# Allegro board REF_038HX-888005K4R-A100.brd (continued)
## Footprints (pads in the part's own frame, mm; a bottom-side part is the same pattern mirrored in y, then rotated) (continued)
PG_VG93K_F_HSM_G1D105_505_ND
  rect 1.626x1.626 smd: A1(-20.32,-3.81) A3(-15.24,-3.81) A5(-10.16,-3.81) A7(-5.08,-3.81) A9(0,-3.81) A11(5.08,-3.81) A13(10.16,-3.81) A15(15.24,-3.81) A17(20.32,-3.81) B2(-17.78,-1.27) B4(-12.7,-1.27) B6(-7.62,-1.27) B8(-2.54,-1.27) B10(2.54,-1.27) B12(7.62,-1.27) B14(12.7,-1.27) B16(17.78,-1.27) C1(-20.32,1.27) C3(-15.24,1.27) C5(-10.16,1.27) C7(-5.08,1.27) C9(0,1.27) C11(5.08,1.27) C13(10.16,1.27) C15(15.24,1.27) C17(20.32,1.27) D2(-17.78,3.81) D4(-12.7,3.81) D6(-7.62,3.81) D8(-2.54,3.81) D10(2.54,3.81) D12(7.62,3.81) D14(12.7,3.81) D16(17.78,3.81)
  round 1.626 smd: A2(-17.78,-3.81) A4(-12.7,-3.81) A6(-7.62,-3.81) A8(-2.54,-3.81) A10(2.54,-3.81) A12(7.62,-3.81) A14(12.7,-3.81) A16(17.78,-3.81) B1(-20.32,-1.27) B3(-15.24,-1.27) B5(-10.16,-1.27) B7(-5.08,-1.27) B9(0,-1.27) B11(5.08,-1.27) B13(10.16,-1.27) B15(15.24,-1.27) B17(20.32,-1.27) C2(-17.78,1.27) C4(-12.7,1.27) C6(-7.62,1.27) C8(-2.54,1.27) C10(2.54,1.27) C12(7.62,1.27) C14(12.7,1.27) C16(17.78,1.27) D3(-15.24,3.81) D5(-10.16,3.81) D7(-5.08,3.81) D9(0,3.81) D11(5.08,3.81) D13(10.16,3.81) D15(15.24,3.81)
PG_VG93K_PF_DPS32_G8D225
  rect 1.778x1.778 hole 0.711: A1(20.32,3.81) A3(15.24,3.81) A5(10.16,3.81) A7(5.08,3.81) A9(0,3.81) A11(-5.08,3.81) A13(-10.16,3.81) A15(-15.24,3.81) B2(17.78,1.27) B4(12.7,1.27) B6(7.62,1.27) B8(2.54,1.27) B10(-2.54,1.27) B12(-7.62,1.27) B14(-12.7,1.27) B16(-17.78,1.27) C1(20.32,-1.27) C3(15.24,-1.27) C5(10.16,-1.27) C7(5.08,-1.27) C9(0,-1.27) C11(-5.08,-1.27) C13(-10.16,-1.27) C15(-15.24,-1.27) D2(17.78,-3.81) D4(12.7,-3.81) D6(7.62,-3.81) D8(2.54,-3.81) D10(-2.54,-3.81) D12(-7.62,-3.81) D14(-12.7,-3.81) D16(-17.78,-3.81)
  round 1.524 hole 0.711: A2(17.78,3.81) A4(12.7,3.81) A6(7.62,3.81) A8(2.54,3.81) A10(-2.54,3.81) A12(-7.62,3.81) A14(-12.7,3.81) A16(-17.78,3.81) A17(-20.32,3.81) B1(20.32,1.27) B3(15.24,1.27) B5(10.16,1.27) B7(5.08,1.27) B9(0,1.27) B11(-5.08,1.27) B13(-10.16,1.27) B15(-15.24,1.27) B17(-20.32,1.27) C2(17.78,-1.27) C4(12.7,-1.27) C6(7.62,-1.27) C8(2.54,-1.27) C10(-2.54,-1.27) C12(-7.62,-1.27) C14(-12.7,-1.27) C16(-17.78,-1.27) C17(-20.32,-1.27) D1(20.32,-3.81) D3(15.24,-3.81) D5(10.16,-3.81) D7(5.08,-3.81) D9(0,-3.81) D11(-5.08,-3.81) D13(-10.16,-3.81) D15(-15.24,-3.81) D17(-20.32,-3.81)
PG_VG93K_PF_DPS32_G8D229
  rect 1.778x1.778 hole 0.711: A1(20.32,3.81) A3(15.24,3.81) A5(10.16,3.81) A7(5.08,3.81) A9(0,3.81) A11(-5.08,3.81) A13(-10.16,3.81) A15(-15.24,3.81) B2(17.78,1.27) B4(12.7,1.27) B6(7.62,1.27) B8(2.54,1.27) B10(-2.54,1.27) B12(-7.62,1.27) B14(-12.7,1.27) B16(-17.78,1.27) C1(20.32,-1.27) C3(15.24,-1.27) C5(10.16,-1.27) C7(5.08,-1.27) C9(0,-1.27) C11(-5.08,-1.27) C13(-10.16,-1.27) C15(-15.24,-1.27) D2(17.78,-3.81) D4(12.7,-3.81) D6(7.62,-3.81) D8(2.54,-3.81) D10(-2.54,-3.81) D12(-7.62,-3.81) D14(-12.7,-3.81) D16(-17.78,-3.81)
  round 1.524 hole 0.711: A2(17.78,3.81) A4(12.7,3.81) A6(7.62,3.81) A8(2.54,3.81) A10(-2.54,3.81) A12(-7.62,3.81) A14(-12.7,3.81) A16(-17.78,3.81) A17(-20.32,3.81) B1(20.32,1.27) B3(15.24,1.27) B5(10.16,1.27) B7(5.08,1.27) B9(0,1.27) B11(-5.08,1.27) B13(-10.16,1.27) B15(-15.24,1.27) B17(-20.32,1.27) C2(17.78,-1.27) C4(12.7,-1.27) C6(7.62,-1.27) C8(2.54,-1.27) C10(-2.54,-1.27) C12(-7.62,-1.27) C14(-12.7,-1.27) C16(-17.78,-1.27) C17(-20.32,-1.27) D1(20.32,-3.81) D3(15.24,-3.81) D5(10.16,-3.81) D7(5.08,-3.81) D9(0,-3.81) D11(-5.08,-3.81) D13(-10.16,-3.81) D15(-15.24,-3.81) D17(-20.32,-3.81)
PG_VG93K_PF_DPS32_G8D425
  rect 1.778x1.778 hole 0.711: A1(20.32,3.81) A3(15.24,3.81) A5(10.16,3.81) A7(5.08,3.81) A9(0,3.81) A11(-5.08,3.81) A13(-10.16,3.81) A15(-15.24,3.81) B2(17.78,1.27) B4(12.7,1.27) B6(7.62,1.27) B8(2.54,1.27) B10(-2.54,1.27) B12(-7.62,1.27) B14(-12.7,1.27) B16(-17.78,1.27) C1(20.32,-1.27) C3(15.24,-1.27) C5(10.16,-1.27) C7(5.08,-1.27) C9(0,-1.27) C11(-5.08,-1.27) C13(-10.16,-1.27) C15(-15.24,-1.27) D2(17.78,-3.81) D4(12.7,-3.81) D6(7.62,-3.81) D8(2.54,-3.81) D10(-2.54,-3.81) D12(-7.62,-3.81) D14(-12.7,-3.81) D16(-17.78,-3.81)
  round 1.524 hole 0.711: A2(17.78,3.81) A4(12.7,3.81) A6(7.62,3.81) A8(2.54,3.81) A10(-2.54,3.81) A12(-7.62,3.81) A14(-12.7,3.81) A16(-17.78,3.81) A17(-20.32,3.81) B1(20.32,1.27) B3(15.24,1.27) B5(10.16,1.27) B7(5.08,1.27) B9(0,1.27) B11(-5.08,1.27) B13(-10.16,1.27) B15(-15.24,1.27) B17(-20.32,1.27) C2(17.78,-1.27) C4(12.7,-1.27) C6(7.62,-1.27) C8(2.54,-1.27) C10(-2.54,-1.27) C12(-7.62,-1.27) C14(-12.7,-1.27) C16(-17.78,-1.27) C17(-20.32,-1.27) D1(20.32,-3.81) D3(15.24,-3.81) D5(10.16,-3.81) D7(5.08,-3.81) D9(0,-3.81) D11(-5.08,-3.81) D13(-10.16,-3.81) D15(-15.24,-3.81) D17(-20.32,-3.81)
PG_VG93K_PF_DPS32_G8D429
  rect 1.778x1.778 hole 0.711: A1(20.32,3.81) A3(15.24,3.81) A5(10.16,3.81) A7(5.08,3.81) A9(0,3.81) A11(-5.08,3.81) A13(-10.16,3.81) A15(-15.24,3.81) B2(17.78,1.27) B4(12.7,1.27) B6(7.62,1.27) B8(2.54,1.27) B10(-2.54,1.27) B12(-7.62,1.27) B14(-12.7,1.27) B16(-17.78,1.27) C1(20.32,-1.27) C3(15.24,-1.27) C5(10.16,-1.27) C7(5.08,-1.27) C9(0,-1.27) C11(-5.08,-1.27) C13(-10.16,-1.27) C15(-15.24,-1.27) D2(17.78,-3.81) D4(12.7,-3.81) D6(7.62,-3.81) D8(2.54,-3.81) D10(-2.54,-3.81) D12(-7.62,-3.81) D14(-12.7,-3.81) D16(-17.78,-3.81)
  round 1.524 hole 0.711: A2(17.78,3.81) A4(12.7,3.81) A6(7.62,3.81) A8(2.54,3.81) A10(-2.54,3.81) A12(-7.62,3.81) A14(-12.7,3.81) A16(-17.78,3.81) A17(-20.32,3.81) B1(20.32,1.27) B3(15.24,1.27) B5(10.16,1.27) B7(5.08,1.27) B9(0,1.27) B11(-5.08,1.27) B13(-10.16,1.27) B15(-15.24,1.27) B17(-20.32,1.27) C2(17.78,-1.27) C4(12.7,-1.27) C6(7.62,-1.27) C8(2.54,-1.27) C10(-2.54,-1.27) C12(-7.62,-1.27) C14(-12.7,-1.27) C16(-17.78,-1.27) C17(-20.32,-1.27) D1(20.32,-3.81) D3(15.24,-3.81) D5(10.16,-3.81) D7(5.08,-3.81) D9(0,-3.81) D11(-5.08,-3.81) D13(-10.16,-3.81) D15(-15.24,-3.81) D17(-20.32,-3.81)
R0402
  custom 0.15x0.15 smd: 1(-0.5,0) 2(0.5,0)
R0603
  rect 0.889x0.889 smd: 1(-0.85,0) 2(0.85,0)
R0805
  rect 1.118x1.372 smd: 1(-0.95,0) 2(0.95,0)
RL_NECEC2_10P_5V
  rect 1.397x1.397 hole 1.041: 1(6.35,2.54)
  round 1.397 hole 1.041: 3(1.27,2.54) 4(-1.27,2.54) 5(-3.81,2.54) 8(-3.81,-2.54) 9(-1.27,-2.54) 10(1.27,-2.54) 12(6.35,-2.54)
RL_NECUA2_5V_V3
  rect 1.524x1.524 hole 1.041: 1(3.6,1.6)
  round 1.524 hole 1.041: 2(0.4,1.6) 3(-1.8,1.6) 4(-4,1.6) 5(-4,-1.6) 6(-1.8,-1.6) 7(0.4,-1.6) 8(3.6,-1.6)
RL_NECUB2_5V
  rect 0.813x3.15 smd: 1(3.8,2.65) 2(0.6,2.65) 3(-1.6,2.65) 4(-3.8,2.65) 5(-3.8,-2.65) 6(-1.6,-2.65) 7(0.6,-2.65) 8(3.8,-2.65)
RL_OMRONG6K2FRF_5V
  rect 0.813x1.803 smd: 1(-3.8,-3.5) 2(-0.6,-3.5) 3(1.6,-3.5) 4(3.8,-3.5) 5(3.8,3.5) 6(1.6,3.5) 7(-0.6,3.5) 8(-3.8,3.5)
  rect 2.007x2.489 smd: G1(-6.2,-1.75) G2(6.2,1.75)
SK_LQFP176P_0P4MM_JG_HX8880
  round 0.508 hole 1.626 unplated: (-16.5,16.5) (-16.5,-16.5) (16.5,16.5) (16.5,-16.5)
  oval 3x0.28 smd: 1(-11.5,8.6) 2(-11.5,8.2) 3(-11.5,7.8) 4(-11.5,7.4) 5(-11.5,7) 6(-11.5,6.6) 7(-11.5,6.2) 8(-11.5,5.8) 9(-11.5,5.4) 10(-11.5,5) 11(-11.5,4.6) 12(-11.5,4.2) 13(-11.5,3.8) 14(-11.5,3.4) 15(-11.5,3) 16(-11.5,2.6) 17(-11.5,2.2) 18(-11.5,1.8) 19(-11.5,1.4) 20(-11.5,1) 21(-11.5,0.6) 22(-11.5,0.2) 23(-11.5,-0.2) 24(-11.5,-0.6) 25(-11.5,-1) 26(-11.5,-1.4) 27(-11.5,-1.8) 28(-11.5,-2.2) 29(-11.5,-2.6) 30(-11.5,-3) 31(-11.5,-3.4) 32(-11.5,-3.8) 33(-11.5,-4.2) 34(-11.5,-4.6) 35(-11.5,-5) 36(-11.5,-5.4) 37(-11.5,-5.8) 38(-11.5,-6.2) 39(-11.5,-6.6) 40(-11.5,-7) 41(-11.5,-7.4) 42(-11.5,-7.8) 43(-11.5,-8.2) 44(-11.5,-8.6) 89(11.5,-8.6) 90(11.5,-8.2) 91(11.5,-7.8) 92(11.5,-7.4) 93(11.5,-7) 94(11.5,-6.6) 95(11.5,-6.2) 96(11.5,-5.8) 97(11.5,-5.4) 98(11.5,-5) 99(11.5,-4.6) 100(11.5,-4.2) 101(11.5,-3.8) 102(11.5,-3.4) 103(11.5,-3) 104(11.5,-2.6) 105(11.5,-2.2) 106(11.5,-1.8) 107(11.5,-1.4) 108(11.5,-1) 109(11.5,-0.6) 110(11.5,-0.2) 111(11.5,0.2) 112(11.5,0.6) 113(11.5,1) 114(11.5,1.4) 115(11.5,1.8) 116(11.5,2.2) 117(11.5,2.6) 118(11.5,3) 119(11.5,3.4) 120(11.5,3.8) 121(11.5,4.2) 122(11.5,4.6) 123(11.5,5) 124(11.5,5.4) 125(11.5,5.8) 126(11.5,6.2) 127(11.5,6.6) 128(11.5,7) 129(11.5,7.4) 130(11.5,7.8) 131(11.5,8.2) 132(11.5,8.6)
  oval 0.28x3 smd: 45(-8.6,-11.5) 46(-8.2,-11.5) 47(-7.8,-11.5) 48(-7.4,-11.5) 49(-7,-11.5) 50(-6.6,-11.5) 51(-6.2,-11.5) 52(-5.8,-11.5) 53(-5.4,-11.5) 54(-5,-11.5) 55(-4.6,-11.5) 56(-4.2,-11.5) 57(-3.8,-11.5) 58(-3.4,-11.5) 59(-3,-11.5) 60(-2.6,-11.5) 61(-2.2,-11.5) 62(-1.8,-11.5) 63(-1.4,-11.5) 64(-1,-11.5) 65(-0.6,-11.5) 66(-0.2,-11.5) 67(0.2,-11.5) 68(0.6,-11.5) 69(1,-11.5) 70(1.4,-11.5) 71(1.8,-11.5) 72(2.2,-11.5) 73(2.6,-11.5) 74(3,-11.5) 75(3.4,-11.5) 76(3.8,-11.5) 77(4.2,-11.5) 78(4.6,-11.5) 79(5,-11.5) 80(5.4,-11.5) 81(5.8,-11.5) 82(6.2,-11.5) 83(6.6,-11.5) 84(7,-11.5) 85(7.4,-11.5) 86(7.8,-11.5) 87(8.2,-11.5) 88(8.6,-11.5) 133(8.6,11.5) 134(8.2,11.5) 135(7.8,11.5) 136(7.4,11.5) 137(7,11.5) 138(6.6,11.5) 139(6.2,11.5) 140(5.8,11.5) 141(5.4,11.5) 142(5,11.5) 143(4.6,11.5) 144(4.2,11.5) 145(3.8,11.5) 146(3.4,11.5) 147(3,11.5) 148(2.6,11.5) 149(2.2,11.5) 150(1.8,11.5) 151(1.4,11.5) 152(1,11.5) 153(0.6,11.5) 154(0.2,11.5) 155(-0.2,11.5) 156(-0.6,11.5) 157(-1,11.5) 158(-1.4,11.5) 159(-1.8,11.5) 160(-2.2,11.5) 161(-2.6,11.5) 162(-3,11.5) 163(-3.4,11.5) 164(-3.8,11.5) 165(-4.2,11.5) 166(-4.6,11.5) 167(-5,11.5) 168(-5.4,11.5) 169(-5.8,11.5) 170(-6.2,11.5) 171(-6.6,11.5) 172(-7,11.5) 173(-7.4,11.5) 174(-7.8,11.5) 175(-8.2,11.5) 176(-8.6,11.5)
  rect 8x8 smd: EP(0,0)
  round 0.508 hole 0.307: G1(-3.3,2.5) G2(-3.3,1.5) G3(-3.3,0.5) G4(-3.3,-0.5) G5(-3.3,-1.5) G6(-3.3,-2.5) G7(3.3,2.5) G8(3.3,1.5) G9(3.3,0.5) G10(3.3,-0.5) G11(3.3,-1.5) G12(3.3,-2.5) G13(-1.8,1.8) G14(-1.8,0.6) G15(-1.8,-0.6) G16(-1.8,-1.8) G17(1.8,1.8) G18(1.8,0.6) G19(1.8,-0.6) G20(1.8,-1.8)
  round 7 hole 4.293: NUT1(-20,20) NUT2(20,20) NUT3(-20,-20) NUT4(20,-20)
SO8_206X050
  rect 1.905x1.143 smd: 1(-2.616,2.095) 4(-2.616,-2.095) 5(2.616,-2.095) 8(2.616,2.095)
  rect 1.905x0.762 smd: 2(-2.616,0.635) 3(-2.616,-0.635) 6(2.616,-0.635) 7(2.616,0.635)
SO8_244X127MM
  rect 1.905x0.508 smd: 1(-3.099,1.905) 2(-3.099,0.635) 3(-3.099,-0.635) 4(-3.099,-1.905) 5(3.099,-1.905) 6(3.099,-0.635) 7(3.099,0.635) 8(3.099,1.905)
SOCKET_BASE_152X152_V0090A
  round 8.128 hole 6.401: NUT1(-70,70) NUT2(70,70) NUT3(70,-70) NUT4(-70,-70)
SOCKET_CODE
  round 0.051 smd: 1(0,0)
SW_4P_UTP0030B-EVB
  rect 1.778x1.778 hole 1.016: 1(-3.175,2.159)
  round 1.778 hole 1.016: 2(3.175,2.159) 3(-3.175,-2.159) 4(3.175,-2.159)
TP_040_T
  round 1.016 smd: 1(0,0)
TPL_040_014_TB
  round 1.016 hole 0.356: 1(0,0)
XTAL_2X2P5MM_4P
  rect 1.143x0.94 smd: 1(-0.825,-0.625) 2(0.825,-0.625) 3(0.825,0.625) 4(-0.825,0.625)
XTAL_3P2X2P5MM_4P_TXC_0201
  rect 1.4x1.2 smd: 1(-1.1,-0.85) 2(1.1,-0.85) 3(1.1,0.85) 4(-1.1,0.85)

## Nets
AGND: 2SH2.1 2SH4.1 2SH6.1 2SH8.1 2SH9.1 2SH11.1 2SH13.1 2SH15.1 2SH17.1 2SH19.1 2SH21.1 2SH24.1 2SH26.1 2SH28.1 BD29.1 BD30.1 BD31.1 BD32.1 BD33.1 BD34.1 BD35.1 BD36.1 BD37.1 BD38.1 BD39.1 BD40.1 C5.2 C6.2 C7.2 C8.2 C9.2 CA1.2 CA2.2 CA3.2 CA4.2 CA5.2 CA6.2 CA7.2 CA8.2 CA9.2 CA10.2 CA11.2 CA12.2 CA13.2 CA14.2 CA15.2 CA16.2 CA17.2 CA18.2 CA19.2 CA20.2 CA21.2 CA22.2 CA23.2 CA24.2 CA25.2 CA26.2 CA27.2 CA28.2 CA29.2 CA30.2 CA31.2 CA32.2 CA33.2 CA34.2 CA35.2 CA36.2 CA37.2 CA38.2 CA39.2 CA40.2 CC1.2 CC2.2 CC4.2 CC6.2 CC7.2 CC8.2 CC9.2 CC11.2 CC13.2 CC15.2 CC16.2 CC17.2 CC19.2 CC20.2 CC22.2 CC23.2 CC25.2 CC26.2 CC27.2 CC28.2 CC29.2 CC30.2 CC31.2 CC32.2 CC33.2 CC34.2 CC35.2 CC36.2 CC37.2 CC38.2 CC39.2 CC40.2 CC41.2 CC42.2 CD1.2 CD3.2 CD4.2 CD5.2 CD6.2 CD7.2 CD8.2 CD9.2 CD10.2 CD11.2 CD12.2 CD13.2 CD14.2 CD15.2 CD16.2 CD17.2 CD18.2 CD19.2 CD20.2 CD21.2 CD22.2 CD23.2 CD24.2 CD25.2 CSDPS225.B2 CSDPS225.B4 CSDPS225.B6 CSDPS225.B8 CSDPS225.B10 CSDPS225.B12 CSDPS225.B14 CSDPS225.B16 CSDPS225.C1 CSDPS225.C3 CSDPS225.C5 CSDPS225.C7 CSDPS225.C9 CSDPS225.C11 CSDPS225.C13 CSDPS225.C15 CSDPS229.B2 CSDPS229.B4 CSDPS229.B6 CSDPS229.B8 CSDPS229.B10 CSDPS229.B12 CSDPS229.B14 CSDPS229.B16 CSDPS229.C1 CSDPS229.C3 CSDPS229.C5 CSDPS229.C7 CSDPS229.C9 CSDPS229.C11 CSDPS229.C13 CSDPS229.C15 CSDPS425.B2 CSDPS425.B4 CSDPS425.B6 CSDPS425.B8 CSDPS425.B10 CSDPS425.B12 CSDPS425.B14 CSDPS425.B16 CSDPS425.C1 CSDPS425.C3 CSDPS425.C5 CSDPS425.C7 CSDPS425.C9 CSDPS425.C11 CSDPS425.C13 CSDPS425.C15 CSDPS429.B2 CSDPS429.B4 CSDPS429.B6 CSDPS429.B8 CSDPS429.B10 CSDPS429.B12 CSDPS429.B14 CSDPS429.B16 CSDPS429.C1 CSDPS429.C3 CSDPS429.C5 CSDPS429.C7 CSDPS429.C9 CSDPS429.C11 CSDPS429.C13 CSDPS429.C15 CT1.1 D102.A1 D102.A2 D102.A3 D102.A4 D102.A5 D102.A6 D102.A7 D102.A8 D102.A9 D102.A10 D102.A11 D102.A12 D102.A13 D102.A14 D102.A15 D102.A16 D102.B1 D102.B2 D102.B3 D102.B4 D102.B5 D102.B6 D102.B7 D102.B8 D102.B9 D102.B10 D102.B11 D102.B12 D102.B13 D102.B14 D102.B15 D102.B16 D103.A1 D103.A2 D103.A3 D103.A4 D103.A5 D103.A6 D103.A7 D103.A8 D103.A9 D103.A10 D103.A11 D103.A12 D103.A13 D103.A14 D103.A15 D103.A16 D103.B1 D103.B2 D103.B3 D103.B4 D103.B5 D103.B6 D103.B7 D103.B8 D103.B9 D103.B10 D103.B11 D103.B12 D103.B13 D103.B14 D103.B15 D103.B16 D104.A1 D104.A2 D104.A3 D104.A4 D104.A5 D104.A6 D104.A7 D104.A8 D104.A9 D104.A10 D104.A11 D104.A12 D104.A13 D104.A14 D104.A15 D104.A16 D104.B1 D104.B2 D104.B3 D104.B4 D104.B5 D104.B6 D104.B7 D104.B8 D104.B9 D104.B10 D104.B11 D104.B12 D104.B13 D104.B14 D104.B15 D104.B16 D106.A1 D106.A2 D106.A3 D106.A4 D106.A5 D106.A6 D106.A7 D106.A8 D106.A9 D106.A10 D106.A11 D106.A12 D106.A13 D106.A14 D106.A15 D106.A16 D106.B1 D106.B2 D106.B3 D106.B4 D106.B5 D106.B6 D106.B7 D106.B8 D106.B9 D106.B10 D106.B11 D106.B12 D106.B13 D106.B14 D106.B15 D106.B16 D107.A1 D107.A2 D107.A3 D107.A4 D107.A5 D107.A6 D107.A7 D107.A8 D107.A9 D107.A10 D107.A11 D107.A12 D107.A13 D107.A14 D107.A15 D107.A16 D107.B1 D107.B2 D107.B3 D107.B4 D107.B5 D107.B6 D107.B7 D107.B8 D107.B9 D107.B10 D107.B11 D107.B12 D107.B13 D107.B14 D107.B15 D107.B16 D108.A1 D108.A2 D108.A3 D108.A4 D108.A5 D108.A6 D108.A7 D108.A8 D108.A9 D108.A10 D108.A11 D108.A12 D108.A13 D108.A14 D108.A15 D108.A16 D108.B1 D108.B2 D108.B3 D108.B4 D108.B5 D108.B6 D108.B7 D108.B8 D108.B9 D108.B10 D108.B11 D108.B12 D108.B13 D108.B14 D108.B15 D108.B16 D109.A1 D109.A2 D109.A3 D109.A4 D109.A5 D109.A6 D109.A7 D109.A8 D109.A9 D109.A10 D109.A11 D109.A12 D109.A13 D109.A14 D109.A15 D109.A16 D109.B1 D109.B2 D109.B3 D109.B4 D109.B5 D109.B6 D109.B7 D109.B8 D109.B9 D109.B10 D109.B11 D109.B12 D109.B13 D109.B14 D109.B15 D109.B16 D110.A1 D110.A2 D110.A3 D110.A4 D110.A5 D110.A6 D110.A7 D110.A8 D110.A9 D110.A10 D110.A11 D110.A12 D110.A13 D110.A14 D110.A15 D110.A16 D110.B1 D110.B2 D110.B3 D110.B4 D110.B5 D110.B6 D110.B7 D110.B8 D110.B9 D110.B10 D110.B11 D110.B12 D110.B13 D110.B14 D110.B15 D110.B16 D111.A1 D111.A2 D111.A3 D111.A4 D111.A5 D111.A6 D111.A7 D111.A8 D111.A9 D111.A10 D111.A11 D111.A12 D111.A13 D111.A14 D111.A15 D111.A16 D111.B1 D111.B2 D111.B3 D111.B4 D111.B5 D111.B6 D111.B7 D111.B8 D111.B9 D111.B10 D111.B11 D111.B12 D111.B13 D111.B14 D111.B15 D111.B16 D112.A1 D112.A2 D112.A3 D112.A4 D112.A5 D112.A6 D112.A7 D112.A8 D112.A9 D112.A10 D112.A11 D112.A12 D112.A13 D112.A14 D112.A15 D112.A16 D112.B1 D112.B2 D112.B3 D112.B4 D112.B5 D112.B6 D112.B7 D112.B8 D112.B9 D112.B10 D112.B11 D112.B12 D112.B13 D112.B14 D112.B15 D112.B16 D113.A1 D113.A2 D113.A3 D113.A4 D113.A5 D113.A6 D113.A7 D113.A8 D113.A9 D113.A10 D113.A11 D113.A12 D113.A13 D113.A14 D113.A15 D113.A16 D113.B1 D113.B2 D113.B3 D113.B4 D113.B5 D113.B6 D113.B7 D113.B8 D113.B9 D113.B10 D113.B11 D113.B12 D113.B13 D113.B14 D113.B15 D113.B16 D114.A1 D114.A2 D114.A3 D114.A4 D114.A5 D114.A6 D114.A7 D114.A8 D114.A9 D114.A10 D114.A11 D114.A12 D114.A13 D114.A14 D114.A15 D114.A16 D114.B1 D114.B2 D114.B3 D114.B4 D114.B5 D114.B6 D114.B7 D114.B8 D114.B9 D114.B10 D114.B11 D114.B12 D114.B13 D114.B14 D114.B15 D114.B16 D115.A1 D115.A2 D115.A3 D115.A4 D115.A5 D115.A6 D115.A7 D115.A8 D115.A9 D115.A10 D115.A11 D115.A12 D115.A13 D115.A14 D115.A15 D115.A16 D115.B1 D115.B2 D115.B3 D115.B4 D115.B5 D115.B6 D115.B7 D115.B8 D115.B9 D115.B10 D115.B11 D115.B12 D115.B13 D115.B14 D115.B15 D115.B16 D116.A1 D116.A2 D116.A3 D116.A4 D116.A5 D116.A6 D116.A7 D116.A8 D116.A9 D116.A10 D116.A11 D116.A12 D116.A13 D116.A14 D116.A15 D116.A16 D116.B1 D116.B2 D116.B3 D116.B4 D116.B5 D116.B6 D116.B7 D116.B8 D116.B9 D116.B10 D116.B11 D116.B12 D116.B13 D116.B14 D116.B15 D116.B16 D117.A1 D117.A2 D117.A3 D117.A4 D117.A5 D117.A6 D117.A7 D117.A8 D117.A9 D117.A10 D117.A11 D117.A12 D117.A13 D117.A14 D117.A15 D117.A16 D117.B1 D117.B2 D117.B3 D117.B4 D117.B5 D117.B6 D117.B7 D117.B8 D117.B9 D117.B10 D117.B11 D117.B12 D117.B13 D117.B14 D117.B15 D117.B16 D118.A1 D118.A2 D118.A3 D118.A4 D118.A5 D118.A6 D118.A7 D118.A8 D118.A9 D118.A10 D118.A11 D118.A12 D118.A13 D118.A14 D118.A15 D118.A16 D118.B1 D118.B2 D118.B3 D118.B4 D118.B5 D118.B6 D118.B7 D118.B8 D118.B9 D118.B10 D118.B11 D118.B12 D118.B13 D118.B14 D118.B15 D118.B16 D119.A1 D119.A2 D119.A3 D119.A4 D119.A5 D119.A6 D119.A7 D119.A8 D119.A9 D119.A10 D119.A11 D119.A12 D119.A13 D119.A14 D119.A15 D119.A16 D119.B1 D119.B2 D119.B3 D119.B4 D119.B5 D119.B6 D119.B7 D119.B8 D119.B9 D119.B10 D119.B11 D119.B12 D119.B13 D119.B14 D119.B15 D119.B16 D120.A1 D120.A2 D120.A3 D120.A4 D120.A5 D120.A6 D120.A7 D120.A8 D120.A9 D120.A10 D120.A11 D120.A12 D120.A13 D120.A14 D120.A15 D120.A16 D120.B1 D120.B2 D120.B3 D120.B4 D120.B5 D120.B6 D120.B7 D120.B8 D120.B9 D120.B10 D120.B11 D120.B12 D120.B13 D120.B14 D120.B15 D120.B16 D121.A1 D121.A2 D121.A3 D121.A4 D121.A5 D121.A6 D121.A7 D121.A8 D121.A9 D121.A10 D121.A11 D121.A12 D121.A13 D121.A14 D121.A15 D121.A16 D121.B1 D121.B2 D121.B3 D121.B4 D121.B5 D121.B6 D121.B7 D121.B8 D121.B9 D121.B10 D121.B11 D121.B12 D121.B13 D121.B14 D121.B15 D121.B16 D122.A1 D122.A2 D122.A3 D122.A4 D122.A5 D122.A6 D122.A7 D122.A8 D122.A9 D122.A10 D122.A11 D122.A12 D122.A13 D122.A14 D122.A15 D122.A16 D122.B1 D122.B2 D122.B3 D122.B4 D122.B5 D122.B6 D122.B7 D122.B8 D122.B9 D122.B10 D122.B11 D122.B12 D122.B13 D122.B14 D122.B15 D122.B16 D123.A1 D123.A2 D123.A3 D123.A4 D123.A5 D123.A6 D123.A7 D123.A8 D123.A9 D123.A10 D123.A11 D123.A12 D123.A13 D123.A14 D123.A15 D123.A16 D123.B1 D123.B2 D123.B3 D123.B4 D123.B5 D123.B6 D123.B7 D123.B8 D123.B9 D123.B10 D123.B11 D123.B12 D123.B13 D123.B14 D123.B15 D123.B16 D124.A1 D124.A2 D124.A3 D124.A4 D124.A5 D124.A6 D124.A7 D124.A8 D124.A9 D124.A10 D124.A11 D124.A12 D124.A13 D124.A14 D124.A15 D124.A16 D124.B1 D124.B2 D124.B3 D124.B4 D124.B5 D124.B6 D124.B7 D124.B8 D124.B9 D124.B10 D124.B11 D124.B12 D124.B13 D124.B14 D124.B15 D124.B16 D226.A1 D226.A2 D226.A3 D226.A4 D226.A5 D226.A6 D226.A7 D226.A8 D226.A9 D226.A10 D226.A11 D226.A12 D226.A13 D226.A14 D226.A15 D226.A16 D226.A17 D226.B1 D226.B2 D226.B3 D226.B4 D226.B5 D226.B6 D226.B7 D226.B8 D226.B9 D226.B10 D226.B11 D226.B12 D226.B13 D226.B14 D226.B15 D226.B16 D226.B17 D227.A1 D227.A2 D227.A3 D227.A4 D227.A5 D227.A6 D227.A7 D227.A8 D227.A9 D227.A10 D227.A11 D227.A12 D227.A13 D227.A14 D227.A15 D227.A16 D227.A17 D227.B1 D227.B2 D227.B3 D227.B4 D227.B5 D227.B6 D227.B7 D227.B8 D227.B9 D227.B10 D227.B11 D227.B12 D227.B13 D227.B14 D227.B15 D227.B16 D227.B17 D228.A1 D228.A2 D228.A3 D228.A4 D228.A5 D228.A6 D228.A7 D228.A8 D228.A9 D228.A10 D228.A11 D228.A12 D228.A13 D228.A14 D228.A15 D228.A16 D228.A17 D228.B1 D228.B2 D228.B3 D228.B4 D228.B5 D228.B6 D228.B7 D228.B8 D228.B9 D228.B10 D228.B11 D228.B12 D228.B13 D228.B14 D228.B15 D228.B16 D228.B17 D230.A1 D230.A2 D230.A3 D230.A4 D230.A5 D230.A6 D230.A7 D230.A8 D230.A9 D230.A10 D230.A11 D230.A12 D230.A13 D230.A14 D230.A15 D230.A16 D230.A17 D230.B1 D230.B2 D230.B3 D230.B4 D230.B5 D230.B6 D230.B7 D230.B8 D230.B9 D230.B10 D230.B11 D230.B12 D230.B13 D230.B14 D230.B15 D230.B16 D230.B17 D231.A1 D231.A2 D231.A3 D231.A4 D231.A5 D231.A6 D231.A7 D231.A8 D231.A9 D231.A10 D231.A11 D231.A12 D231.A13 D231.A14 D231.A15 D231.A16 D231.A17 D231.B1 D231.B2 D231.B3 D231.B4 D231.B5 D231.B6 D231.B7 D231.B8 D231.B9 D231.B10 D231.B11 D231.B12 D231.B13 D231.B14 D231.B15 D231.B16 D231.B17 D232.A1 D232.A2 D232.A3 D232.A4 D232.A5 D232.A6 D232.A7 D232.A8 D232.A9 D232.A10 D232.A11 D232.A12 D232.A13 D232.A14 D232.A15 D232.A16 D232.A17 D232.B1 D232.B2 D232.B3 D232.B4 D232.B5 D232.B6 D232.B7 D232.B8 D232.B9 D232.B10 D232.B11 D232.B12 D232.B13 D232.B14 D232.B15 D232.B16 D232.B17 D301.A1 D301.A2 D301.A3 D301.A4 D301.A5 D301.A6 D301.A7 D301.A8 D301.A9 D301.A10 D301.A11 D301.A12 D301.A13 D301.A14 D301.A15 D301.A16 D301.B1 D301.B2 D301.B3 D301.B4 D301.B5 D301.B6 D301.B7 D301.B8 D301.B9 D301.B10 D301.B11 D301.B12 D301.B13 D301.B14 D301.B15 D301.B16 D302.A1 D302.A2 D302.A3 D302.A4 D302.A5 D302.A6 D302.A7 D302.A8 D302.A9 D302.A10 D302.A11 D302.A12 D302.A13 D302.A14 D302.A15 D302.A16 D302.B1 D302.B2 D302.B3 D302.B4 D302.B5 D302.B6 D302.B7 D302.B8 D302.B9 D302.B10 D302.B11 D302.B12 D302.B13 D302.B14 D302.B15 D302.B16 D305.A1 D305.A2 D305.A3 D305.A4 D305.A5 D305.A6 D305.A7 D305.A8 D305.A9 D305.A10 D305.A11 D305.A12 D305.A13 D305.A14 D305.A15 D305.A16 D305.B1 D305.B2 D305.B3 D305.B4 D305.B5 D305.B6 D305.B7 D305.B8 D305.B9 D305.B10 D305.B11 D305.B12 D305.B13 D305.B14 D305.B15 D305.B16 D306.A1 D306.A2 D306.A3 D306.A4 D306.A5 D306.A6 D306.A7 D306.A8 D306.A9 D306.A10 D306.A11 D306.A12 D306.A13 D306.A14 D306.A15 D306.A16 D306.B1 D306.B2 D306.B3 D306.B4 D306.B5 D306.B6 D306.B7 D306.B8 D306.B9 D306.B10 D306.B11 D306.B12 D306.B13 D306.B14 D306.B15 D306.B16 D426.A1 D426.A2 D426.A3 D426.A4 D426.A5 D426.A6 D426.A7 D426.A8 D426.A9 D426.A10 D426.A11 D426.A12 D426.A13 D426.A14 D426.A15 D426.A16 D426.A17 D426.B1 D426.B2 D426.B3 D426.B4 D426.B5 D426.B6 D426.B7 D426.B8 D426.B9 D426.B10 D426.B11 D426.B12 D426.B13 D426.B14 D426.B15 D426.B16 D426.B17 D427.A1 D427.A2 D427.A3 D427.A4 D427.A5 D427.A6 D427.A7 D427.A8 D427.A9 D427.A10 D427.A11 D427.A12 D427.A13 D427.A14 D427.A15 D427.A16 D427.A17 D427.B1 D427.B2 D427.B3 D427.B4 D427.B5 D427.B6 D427.B7 D427.B8 D427.B9 D427.B10 D427.B11 D427.B12 D427.B13 D427.B14 D427.B15 D427.B16 D427.B17 D428.A1 D428.A2 D428.A3 D428.A4 D428.A5 D428.A6 D428.A7 D428.A8 D428.A9 D428.A10 D428.A11 D428.A12 D428.A13 D428.A14 D428.A15 D428.A16 D428.A17 D428.B1 D428.B2 D428.B3 D428.B4 D428.B5 D428.B6 D428.B7 D428.B8 D428.B9 D428.B10 D428.B11 D428.B12 D428.B13 D428.B14 D428.B15 D428.B16 D428.B17 D430.A1 D430.A2 D430.A3 D430.A4 D430.A5 D430.A6 D430.A7 D430.A8 D430.A9 D430.A10 D430.A11 D430.A12 D430.A13 D430.A14 D430.A15 D430.A16 D430.A17 D430.B1 D430.B2 D430.B3 D430.B4 D430.B5 D430.B6 D430.B7 D430.B8 D430.B9 D430.B10 D430.B11 D430.B12 D430.B13 D430.B14 D430.B15 D430.B16 D430.B17 D431.A1 D431.A2 D431.A3 D431.A4 D431.A5 D431.A6 D431.A7 D431.A8 D431.A9 D431.A10 D431.A11 D431.A12 D431.A13 D431.A14 D431.A15 D431.A16 D431.A17 D431.B1 D431.B2 D431.B3 D431.B4 D431.B5 D431.B6 D431.B7 D431.B8 D431.B9 D431.B10 D431.B11 D431.B12 D431.B13 D431.B14 D431.B15 D431.B16 D431.B17 D432.A1 D432.A2 D432.A3 D432.A4 D432.A5 D432.A6 D432.A7 D432.A8 D432.A9 D432.A10 D432.A11 D432.A12 D432.A13 D432.A14 D432.A15 D432.A16 D432.A17 D432.B1 D432.B2 D432.B3 D432.B4 D432.B5 D432.B6 D432.B7 D432.B8 D432.B9 D432.B10 D432.B11 D432.B12 D432.B13 D432.B14 D432.B15 D432.B16 D432.B17 DPS1.A01 DPS1.A05 DPS1.A11 DPS1.A15 DPS2.A01 DPS2.A05 DPS2.A11 DPS2.A15 DPS3.A01 DPS3.A05 DPS3.A11 DPS3.A15 DPS8.A01 DPS8.A05 DPS8.A11 DPS8.A15 GND1.1(TP) GND2.1(TP) GND3.1(TP) GND4.1(TP) GND5.1(TP) GND6.1(TP) GND7.1(TP) GND8.1(TP) GND9.1(TP) GND10.1(TP) GND11.1(TP) GND12.1(TP) GND13.1(TP) GND14.1(TP) K1.G1(GND#G1) K1.G2(GND#G2) K2.G1(GND#G1) K2.G2(GND#G2) K3.G1(GND#G1) K3.G2(GND#G2) K4.G1(GND#G1) K4.G2(GND#G2) K5.G1(GND#G1) K5.G2(GND#G2) K6.G1(GND#G1) K6.G2(GND#G2) K7.G1(GND#G1) K7.G2(GND#G2) K8.G1(GND#G1) K8.G2(GND#G2) K11.G1(GND#G1) K11.G2(GND#G2) K16.G1(GND#G1) K16.G2(GND#G2) K17.G1(GND#G1) K17.G2(GND#G2) K21.G1(GND#G1) K21.G2(GND#G2) K22.G1(GND#G1) K22.G2(GND#G2) K23.G1(GND#G1) K23.G2(GND#G2) K24.G1(GND#G1) K24.G2(GND#G2) K25.G1(GND#G1) K25.G2(GND#G2) K26.G1(GND#G1) K26.G2(GND#G2) K27.G1(GND#G1) K27.G2(GND#G2) K29.G1(GND#G1) K29.G2(GND#G2) K30.G1(GND#G1) K30.G2(GND#G2) R2.1 R3.2 R86.2 R93.2 R117.2 R131.2 R132.2 RT3.2 RT4.2 RT9.2 S1_I2C.4 SB1.1 SB2.1 SB3.1 SB8.1 SH2.1 SH4.1 SH6.1 SH8.1 SH9.1 SH11.1 SH13.1 SH15.1 SH17.1 SH19.1 SH21.1 SH24.1 SH26.1 SH28.1 SITE1.4(GND-1) SITE1.23(VSS-1) SITE1.28(AVSS-1) SITE1.34(AVSS-2) SITE1.38(GND-2) SITE1.62(VSS-2) SITE1.108(GND-3) SITE1.128(GND-4) SITE1.146(VSS11_C) SITE1.EP(EP(GND)) SITE1.G1 SITE1.G2 SITE1.G3 SITE1.G4 SITE1.G5 SITE1.G6 SITE1.G7 SITE1.G8 SITE1.G9 SITE1.G10 SITE1.G11 SITE1.G12 SITE1.G13 SITE1.G14 SITE1.G15 SITE1.G16 SITE1.G17 SITE1.G18 SITE1.G19 SITE1.G20 SITE2.4(GND-1) SITE2.23(VSS-1) SITE2.28(AVSS-1) SITE2.34(AVSS-2) SITE2.38(GND-2) SITE2.62(VSS-2) SITE2.108(GND-3) SITE2.128(GND-4) SITE2.146(VSS11_C) SITE2.EP(EP(GND)) SITE2.G1 SITE2.G2 SITE2.G3 SITE2.G4 SITE2.G5 SITE2.G6 SITE2.G7 SITE2.G8 SITE2.G9 SITE2.G10 SITE2.G11 SITE2.G12 SITE2.G13 SITE2.G14 SITE2.G15 SITE2.G16 SITE2.G17 SITE2.G18 SITE2.G19 SITE2.G20 SW1.1 SW1.2 U1.4(GND) U2.4(GND) UNK2C5.2 UNK2C6.2 UNK2C7.2 UNK2C8.2 UNK2C9.2 UNK2CA1.2 UNK2CA2.2 UNK2CA3.2 UNK2CA4.2 UNK2CA5.2 UNK2CA6.2 UNK2CA7.2 UNK2CA8.2 UNK2CA9.2 UNK2CA10.2 UNK2CA11.2 UNK2CA12.2 UNK2CA13.2 UNK2CA14.2 UNK2CA15.2 UNK2CA16.2 UNK2CA17.2 UNK2CA18.2 UNK2CA19.2 UNK2CA20.2 UNK2CA21.2 UNK2CA22.2 UNK2CA23.2 UNK2CA24.2 UNK2CA25.2 UNK2CA26.2 UNK2CA27.2 UNK2CA28.2 UNK2CA29.2 UNK2CA30.2 UNK2CA31.2 UNK2CA32.2 UNK2CA33.2 UNK2CA34.2 UNK2CA35.2 UNK2CA36.2 UNK2CA37.2 UNK2CA38.2 UNK2CA39.2 UNK2CA40.2 UNK2CC1.2 UNK2CC2.2 UNK2CC4.2 UNK2CC6.2 UNK2CC7.2 UNK2CC8.2 UNK2CC9.2 UNK2CC11.2 UNK2CC13.2 UNK2CC15.2 UNK2CC16.2 UNK2CC17.2 UNK2CC19.2 UNK2CC20.2 UNK2CC22.2 UNK2CC23.2 UNK2CC25.2 UNK2CC26.2 UNK2CC27.2 UNK2CC28.2 UNK2CC29.2 UNK2CC30.2 UNK2CC31.2 UNK2CC32.2 UNK2CC33.2 UNK2CC34.2 UNK2CC35.2 UNK2CC36.2 UNK2CC37.2 UNK2CC38.2 UNK2CC39.2 UNK2CC40.2 UNK2CC41.2 UNK2CC42.2 UNK2CD1.2 UNK2CD3.2 UNK2CD4.2 UNK2CD5.2 UNK2CD6.2 UNK2CD7.2 UNK2CD8.2 UNK2CD9.2 UNK2CD10.2 UNK2CD11.2 UNK2CD12.2 UNK2CD13.2 UNK2CD14.2 UNK2CD15.2 UNK2CD16.2 UNK2CD17.2 UNK2CD18.2 UNK2CD19.2 UNK2CD20.2 UNK2CD21.2 UNK2CD22.2 UNK2CD23.2 UNK2CD24.2 UNK2CD25.2 UNK2CT1.1 UNK2GND1.1 UNK2GND2.1 UNK2GND3.1 UNK2GND4.1 UNK2GND5.1 UNK2GND6.1 UNK2GND7.1 UNK2GND8.1 UNK2GND9.1 UNK2GND10.1 UNK2GND11.1 UNK2GND12.1 UNK2GND13.1 UNK2GND14.1 UNK2K1.G1 UNK2K1.G2 UNK2K2.G1 UNK2K2.G2 UNK2K3.G1 UNK2K3.G2 UNK2K4.G1 UNK2K4.G2 UNK2K5.G1 UNK2K5.G2 UNK2K6.G1 UNK2K6.G2 UNK2K7.G1 UNK2K7.G2 UNK2K8.G1 UNK2K8.G2 UNK2K11.G1 UNK2K11.G2 UNK2K16.G1 UNK2K16.G2 UNK2K17.G1 UNK2K17.G2 UNK2K21.G1 UNK2K21.G2 UNK2K22.G1 UNK2K22.G2 UNK2K23.G1 UNK2K23.G2 UNK2K24.G1 UNK2K24.G2 UNK2K25.G1 UNK2K25.G2 UNK2K26.G1 UNK2K26.G2 UNK2K27.G1 UNK2K27.G2 UNK2K29.G1 UNK2K29.G2 UNK2K30.G1 UNK2K30.G2 UNK2R2.1 UNK2R3.2 UNK2R86.2 UNK2R93.2 UNK2R117.2 UNK2R131.2 UNK2R132.2 UNK2RT3.2 UNK2RT4.2 UNK2RT9.2 UNK2S1_I2C.4 UNK2U1.4 UNK2U2.4 UNK2UT1.7 UNK2Y1.2 UNK2Y1.4 UNK2Y2.2 UNK2Y2.4 UT1.7(GND) Y1.2 Y1.4 Y2.2 Y2.4
1SK1_2: UNK1SK1_2.1 UNK2SK1.2
1SK1_3: UNK1SK1_3.1 UNK2SK1.3
1SK1_4: UNK1SK1_4.1 UNK2SK1.4
1SK1_5: UNK1SK1_5.1 UNK2SK1.5
1SK1_6: UNK1SK1_6.1 UNK2SK1.6
1SK1_7: UNK1SK1_7.1 UNK2SK1.7
1SK2_2: UNK1SK2_2.1 UNK2SK2.2
1SK2_3: UNK1SK2_3.1 UNK2SK2.3
1SK2_4: UNK1SK2_4.1 UNK2SK2.4
1SK2_5: UNK1SK2_5.1 UNK2SK2.5
1SK2_6: UNK1SK2_6.1 UNK2SK2.6
1SK2_7: UNK1SK2_7.1 UNK2SK2.7
CSDPS225GS1: CSDPS225.D2 SH2.2
CSDPS225GS2: CSDPS225.A1
CSDPS225GS3: CSDPS225.D4 SH24.2
CSDPS225GS4: CSDPS225.A3
CSDPS225GS5: CSDPS225.D6 SH13.2
CSDPS225GS6: CSDPS225.A5
CSDPS225GS7: CSDPS225.D8 SH8.2
CSDPS225GS8: CSDPS225.A7
CSDPS225GS9: CSDPS225.D10 SH26.2
CSDPS225GS10: CSDPS225.A9
CSDPS225GS11: CSDPS225.D12 SH15.2
CSDPS225GS12: CSDPS225.A11
CSDPS225GS13: CSDPS225.A13 CSDPS225.D14 CSDPS225.D16 SH6.2
CSDPS225GS16: CSDPS225.A15
CSDPS225P1: CA1.1 CA2.1 CC1.1 CC2.1 CD1.1 CSDPS225.B1 K34.4 RP1.1 SH1.1 SITE1.3(VDDA_33_LV) TP_VDDA_33_LV.1(TP)
CSDPS225P2: CSDPS225.C2
CSDPS225P3: CA32.1 CA33.1 CC26.1 CD16.1 CSDPS225.B3 K31.4 RP10.1 SH23.1 SITE1.105(AVDD11_XTAL) TP_AVDD11_XTAL.1(TP)
CSDPS225P4: CSDPS225.C4
CSDPS225P5: CA13.1 CA14.1 CC19.1 CC20.1 CD13.1 CSDPS225.B5 K40.4 RP7.1 SH14.1 SITE1.106(PLL_M_VDD33) TP_PLL_M_VDD33.1(TP)
CSDPS225P6: CSDPS225.C6
CSDPS225P7: CA7.1 CA8.1 CC11.1 CD8.1 CSDPS225.B7 K37.4 RP4.1 SH7.1 SITE1.25(AVDD18_RX) TP_AVDD18_RX.1(TP)
CSDPS225P8: CSDPS225.C8
CSDPS225P9: CA35.1 CA36.1 CC17.1 CC29.1 CC37.1 CC38.1 CD12.1 CD24.1 CSDPS225.B9 K39.9 RP11.1 SH25.1 SITE1.119(VDDTXPST_11_T-1) SITE1.139(VDDTXPST_11_T-2) TP_VDDTXPST_11_T.1(TP)
CSDPS225P10: CSDPS225.C10
CSDPS225P11: CA15.1 CA16.1 CC22.1 CC23.1 CD14.1 CSDPS225.B11 K40.9 RP8.1 SH16.1 SITE1.111(PLL_TX_VDD33) TP_PLL_TX_VDD33.1(TP)
CSDPS225P12: CSDPS225.C12
CSDPS225P13: CA5.1 CA6.1 CC6.1 CC7.1 CC8.1 CC9.1 CC36.1 CD4.1 CD5.1 CD6.1 CD7.1 CD23.1 CSDPS225.B13 CSDPS225.B15 CSDPS225.C14 K36.4 K36.9 RP3.1 SH5.1 SITE1.22(VDDC_11-1) SITE1.39(VDDC_11-2) SITE1.64(VDDC_11-3) SITE1.104(VDDC_11-4) SITE1.147(VDDC_11-5) TP_VDDC_11.1(TP)
CSDPS225P16: CSDPS225.C16
CSDPS225PS1: CSDPS225.D1 SH1.2
CSDPS225PS2: CSDPS225.A2
CSDPS225PS3: CSDPS225.D3 SH23.2
CSDPS225PS4: CSDPS225.A4
CSDPS225PS5: CSDPS225.D5 SH14.2
CSDPS225PS6: CSDPS225.A6
CSDPS225PS7: CSDPS225.D7 SH7.2
CSDPS225PS8: CSDPS225.A8
CSDPS225PS9: CSDPS225.D9 SH25.2
CSDPS225PS10: CSDPS225.A10
CSDPS225PS11: CSDPS225.D11 SH16.2
CSDPS225PS12: CSDPS225.A12
CSDPS225PS13: CSDPS225.A14 CSDPS225.D13 CSDPS225.D15 SH5.2
CSDPS225PS16: CSDPS225.A16
CSDPS229GS1: 2SH2.2 CSDPS229.D2
CSDPS229GS2: CSDPS229.A1
CSDPS229GS3: 2SH24.2 CSDPS229.D4
CSDPS229GS4: CSDPS229.A3
CSDPS229GS5: 2SH13.2 CSDPS229.D6
CSDPS229GS6: CSDPS229.A5
CSDPS229GS7: 2SH8.2 CSDPS229.D8
CSDPS229GS8: CSDPS229.A7
CSDPS229GS9: 2SH26.2 CSDPS229.D10
CSDPS229GS10: CSDPS229.A9
CSDPS229GS11: 2SH15.2 CSDPS229.D12
CSDPS229GS12: CSDPS229.A11
CSDPS229GS13: 2SH6.2 CSDPS229.A13 CSDPS229.D14 CSDPS229.D16
CSDPS229GS16: CSDPS229.A15
CSDPS229P1: 2SH1.1 CSDPS229.B1 SITE2.3(VDDA_33_LV) UNK2CA1.1 UNK2CA2.1 UNK2CC1.1 UNK2CC2.1 UNK2CD1.1 UNK2K34.4 UNK2RP1.1 UNK2TP_VDDA_33_LV.1
CSDPS229P2: CSDPS229.C2
CSDPS229P3: 2SH23.1 CSDPS229.B3 SITE2.105(AVDD11_XTAL) UNK2CA32.1 UNK2CA33.1 UNK2CC26.1 UNK2CD16.1 UNK2K31.4 UNK2RP10.1 UNK2TP_AVDD11_XTAL.1
CSDPS229P4: CSDPS229.C4
CSDPS229P5: 2SH14.1 CSDPS229.B5 SITE2.106(PLL_M_VDD33) UNK2CA13.1 UNK2CA14.1 UNK2CC19.1 UNK2CC20.1 UNK2CD13.1 UNK2K40.4 UNK2RP7.1 UNK2TP_PLL_M_VDD33.1
CSDPS229P6: CSDPS229.C6
CSDPS229P7: 2SH7.1 CSDPS229.B7 SITE2.25(AVDD18_RX) UNK2CA7.1 UNK2CA8.1 UNK2CC11.1 UNK2CD8.1 UNK2K37.4 UNK2RP4.1 UNK2TP_AVDD18_RX.1
CSDPS229P8: CSDPS229.C8
CSDPS229P9: 2SH25.1 CSDPS229.B9 SITE2.119(VDDTXPST_11_T-1) SITE2.139(VDDTXPST_11_T-2) UNK2CA35.1 UNK2CA36.1 UNK2CC17.1 UNK2CC29.1 UNK2CC37.1 UNK2CC38.1 UNK2CD12.1 UNK2CD24.1 UNK2K39.9 UNK2RP11.1 UNK2TP_VDDTXPST_11_T.1
CSDPS229P10: CSDPS229.C10
CSDPS229P11: 2SH16.1 CSDPS229.B11 SITE2.111(PLL_TX_VDD33) UNK2CA15.1 UNK2CA16.1 UNK2CC22.1 UNK2CC23.1 UNK2CD14.1 UNK2K40.9 UNK2RP8.1 UNK2TP_PLL_TX_VDD33.1
CSDPS229P12: CSDPS229.C12
CSDPS229P13: 2SH5.1 CSDPS229.B13 CSDPS229.B15 CSDPS229.C14 SITE2.22(VDDC_11-1) SITE2.39(VDDC_11-2) SITE2.64(VDDC_11-3) SITE2.104(VDDC_11-4) SITE2.147(VDDC_11-5) UNK2CA5.1 UNK2CA6.1 UNK2CC6.1 UNK2CC7.1 UNK2CC8.1 UNK2CC9.1 UNK2CC36.1 UNK2CD4.1 UNK2CD5.1 UNK2CD6.1 UNK2CD7.1 UNK2CD23.1 UNK2K36.4 UNK2K36.9 UNK2RP3.1 UNK2TP_VDDC_11.1
CSDPS229P16: CSDPS229.C16
CSDPS229PS1: 2SH1.2 CSDPS229.D1
CSDPS229PS2: CSDPS229.A2
CSDPS229PS3: 2SH23.2 CSDPS229.D3
CSDPS229PS4: CSDPS229.A4
CSDPS229PS5: 2SH14.2 CSDPS229.D5
CSDPS229PS6: CSDPS229.A6
CSDPS229PS7: 2SH7.2 CSDPS229.D7
CSDPS229PS8: CSDPS229.A8
CSDPS229PS9: 2SH25.2 CSDPS229.D9
CSDPS229PS10: CSDPS229.A10
CSDPS229PS11: 2SH16.2 CSDPS229.D11
CSDPS229PS12: CSDPS229.A12
CSDPS229PS13: 2SH5.2 CSDPS229.A14 CSDPS229.D13 CSDPS229.D15
CSDPS229PS16: CSDPS229.A16
CSDPS425GS1: CSDPS425.D2 SH11.2
CSDPS425GS2: CSDPS425.A1
CSDPS425GS3: CSDPS425.D4 SH19.2
CSDPS425GS4: CSDPS425.A3
CSDPS425GS5: CSDPS425.D6
CSDPS425GS6: CSDPS425.A5
CSDPS425GS7: CSDPS425.D8 SH17.2
CSDPS425GS8: CSDPS425.A7
CSDPS425GS9: CSDPS425.D10 SH21.2
CSDPS425GS10: CSDPS425.A9
CSDPS425GS11: CSDPS425.D12 SH4.2
CSDPS425GS12: CSDPS425.A11
CSDPS425GS13: CSDPS425.D14 SH9.2
CSDPS425GS14: CSDPS425.A13
CSDPS425GS15: CSDPS425.D16 SH28.2
CSDPS425GS16: CSDPS425.A15
CSDPS425P1: CA11.1 CA12.1 CC15.1 CC16.1 CC27.1 CC28.1 CD10.1 CD11.1 CSDPS425.B1 K39.4 RP6.1 SH12.1 SITE1.78(VDDTXPST_11_B-1) SITE1.97(VDDTXPST_11_B-2) TP_VDDTXPST_11_B.1(TP)
CSDPS425P2: CSDPS425.C2
CSDPS425P3: CA19.1 CA20.1 CSDPS425.B3 R1.1 R4.1 SH20.1 TP_AUXVCC.1(TP)
CSDPS425P4: CSDPS425.C4
CSDPS425P5: CSDPS425.B5
CSDPS425P6: CSDPS425.C6
CSDPS425P7: CA17.1 CA18.1 CC25.1 CC40.1 CD15.1 CSDPS425.B7 K42.4 RP9.1 SH18.1 SITE1.72(VDD_TXREG_33_B) TP_VDD_TXREG_33_B.1(TP)
CSDPS425P8: CSDPS425.C8
CSDPS425P9: C8.1 C9.1 CA30.1 CA31.1 CSDPS425.B9 R82.2 R83.1 R84.1 R87.2 R88.2 R89.2 R90.2 R91.2 R92.2 R94.2 R95.2 R96.2 R97.2 R98.2 R99.2 R119.1 R120.1 SH22.1 TP_VCC3V3.1(TP) U1.8(VCC) U2.8(VCC)
CSDPS425P10: CSDPS425.C10
CSDPS425P11: CA3.1 CA4.1 CC4.1 CC30.1 CC31.1 CC32.1 CC33.1 CC34.1 CC35.1 CC42.1 CD3.1 CD17.1 CD18.1 CD19.1 CD20.1 CD21.1 CD22.1 CSDPS425.B11 K34.9 R85.1 RP2.1 SH3.1 SITE1.17(VDD_IO_33-1) SITE1.37(VDD_IO_33-2) SITE1.63(VDD_IO_33-3) SITE1.71(VDD_IO_33-4) SITE1.107(VDD_IO_33-5) SITE1.145(VDD_IO_33-6) SITE1.162(VDD_IO_33-7) TP_VDD_IO_33.1(TP)
CSDPS425P12: CSDPS425.C12
CSDPS425P13: CA9.1 CA10.1 CC13.1 CD9.1 CSDPS425.B13 K37.9 RP5.1 SH10.1 SITE1.31(AVDD11_RX) TP_AVDD11_RX.1(TP)
CSDPS425P14: CSDPS425.C14
CSDPS425P15: CA38.1 CA39.1 CC39.1 CC41.1 CD25.1 CSDPS425.B15 K42.9 RP12.1 SH27.1 SITE1.144(VDD_TXREG_33_T) TP_VDD_TXREG_33_T.1(TP)
CSDPS425P16: CSDPS425.C16
CSDPS425PS1: CSDPS425.D1 SH12.2
CSDPS425PS2: CSDPS425.A2
CSDPS425PS3: CSDPS425.D3 SH20.2
CSDPS425PS4: CSDPS425.A4
CSDPS425PS5: CSDPS425.D5
CSDPS425PS6: CSDPS425.A6
CSDPS425PS7: CSDPS425.D7 SH18.2
CSDPS425PS8: CSDPS425.A8
CSDPS425PS9: CSDPS425.D9 SH22.2
CSDPS425PS10: CSDPS425.A10
CSDPS425PS11: CSDPS425.D11 SH3.2
CSDPS425PS12: CSDPS425.A12
CSDPS425PS13: CSDPS425.D13 SH10.2
CSDPS425PS14: CSDPS425.A14
CSDPS425PS15: CSDPS425.D15 SH27.2
CSDPS425PS16: CSDPS425.A16
CSDPS429GS1: 2SH11.2 CSDPS429.D2
CSDPS429GS2: CSDPS429.A1
CSDPS429GS3: CSDPS429.D4
CSDPS429GS4: CSDPS429.A3
CSDPS429GS5: 2SH19.2 CSDPS429.D6
CSDPS429GS6: CSDPS429.A5
CSDPS429GS7: 2SH17.2 CSDPS429.D8
CSDPS429GS8: CSDPS429.A7
CSDPS429GS9: 2SH21.2 CSDPS429.D10
CSDPS429GS10: CSDPS429.A9
CSDPS429GS11: 2SH4.2 CSDPS429.D12
CSDPS429GS12: CSDPS429.A11
CSDPS429GS13: 2SH9.2 CSDPS429.D14
CSDPS429GS14: CSDPS429.A13
CSDPS429GS15: 2SH28.2 CSDPS429.D16
CSDPS429GS16: CSDPS429.A15
CSDPS429P1: 2SH12.1 CSDPS429.B1 SITE2.78(VDDTXPST_11_B-1) SITE2.97(VDDTXPST_11_B-2) UNK2CA11.1 UNK2CA12.1 UNK2CC15.1 UNK2CC16.1 UNK2CC27.1 UNK2CC28.1 UNK2CD10.1 UNK2CD11.1 UNK2K39.4 UNK2RP6.1 UNK2TP_VDDTXPST_11_B.1
CSDPS429P2: CSDPS429.C2
CSDPS429P3: CSDPS429.B3
CSDPS429P4: CSDPS429.C4
CSDPS429P5: 2SH20.1 CSDPS429.B5 UNK2CA19.1 UNK2CA20.1 UNK2R1.1 UNK2R4.1 UNK2TP_AUXVCC.1
CSDPS429P6: CSDPS429.C6
CSDPS429P7: 2SH18.1 CSDPS429.B7 SITE2.72(VDD_TXREG_33_B) UNK2CA17.1 UNK2CA18.1 UNK2CC25.1 UNK2CC40.1 UNK2CD15.1 UNK2K42.4 UNK2RP9.1 UNK2TP_VDD_TXREG_33_B.1
CSDPS429P8: CSDPS429.C8
CSDPS429P9: 2SH22.1 CSDPS429.B9 UNK2C8.1 UNK2C9.1 UNK2CA30.1 UNK2CA31.1 UNK2R82.2 UNK2R83.1 UNK2R84.1 UNK2R87.2 UNK2R88.2 UNK2R89.2 UNK2R90.2 UNK2R91.2 UNK2R92.2 UNK2R94.2 UNK2R95.2 UNK2R96.2 UNK2R97.2 UNK2R98.2 UNK2R99.2 UNK2R119.1 UNK2R120.1 UNK2TP_VCC3V3.1 UNK2U1.8 UNK2U2.8
CSDPS429P10: CSDPS429.C10
CSDPS429P11: 2SH3.1 CSDPS429.B11 SITE2.17(VDD_IO_33-1) SITE2.37(VDD_IO_33-2) SITE2.63(VDD_IO_33-3) SITE2.71(VDD_IO_33-4) SITE2.107(VDD_IO_33-5) SITE2.145(VDD_IO_33-6) SITE2.162(VDD_IO_33-7) UNK2CA3.1 UNK2CA4.1 UNK2CC4.1 UNK2CC30.1 UNK2CC31.1 UNK2CC32.1 UNK2CC33.1 UNK2CC34.1 UNK2CC35.1 UNK2CC42.1 UNK2CD3.1 UNK2CD17.1 UNK2CD18.1 UNK2CD19.1 UNK2CD20.1 UNK2CD21.1 UNK2CD22.1 UNK2K34.9 UNK2R85.1 UNK2RP2.1 UNK2TP_VDD_IO_33.1
CSDPS429P12: CSDPS429.C12
CSDPS429P13: 2SH10.1 CSDPS429.B13 SITE2.31(AVDD11_RX) UNK2CA9.1 UNK2CA10.1 UNK2CC13.1 UNK2CD9.1 UNK2K37.9 UNK2RP5.1 UNK2TP_AVDD11_RX.1
CSDPS429P14: CSDPS429.C14
CSDPS429P15: 2SH27.1 CSDPS429.B15 SITE2.144(VDD_TXREG_33_T) UNK2CA38.1 UNK2CA39.1 UNK2CC39.1 UNK2CC41.1 UNK2CD25.1 UNK2K42.9 UNK2RP12.1 UNK2TP_VDD_TXREG_33_T.1
CSDPS429P16: CSDPS429.C16
CSDPS429PS1: 2SH12.2 CSDPS429.D1
CSDPS429PS2: CSDPS429.A2
CSDPS429PS3: CSDPS429.D3
CSDPS429PS4: CSDPS429.A4
CSDPS429PS5: 2SH20.2 CSDPS429.D5
CSDPS429PS6: CSDPS429.A6
CSDPS429PS7: 2SH18.2 CSDPS429.D7
CSDPS429PS8: CSDPS429.A8
CSDPS429PS9: 2SH22.2 CSDPS429.D9
CSDPS429PS10: CSDPS429.A10
CSDPS429PS11: 2SH3.2 CSDPS429.D11
CSDPS429PS12: CSDPS429.A12
CSDPS429PS13: 2SH10.2 CSDPS429.D13
CSDPS429PS14: CSDPS429.A14
CSDPS429PS15: 2SH27.2 CSDPS429.D15
CSDPS429PS16: CSDPS429.A16
D231_MCB1_CT2: D231.17
D231_MCB1_E+: D231.16
D231_MCB1_E-: D231.15
D231_MCB1_EE+: D231.08
D231_MCB1_EE-: D231.07
D231_MCB1_F+: D231.14
D231_MCB1_F-: D231.13
D231_MCB1_FF+: D231.06
D231_MCB1_FF-: D231.05
D231_MCB1_G+: D231.12
D231_MCB1_G-: D231.11
D231_MCB1_GG+: D231.04
D231_MCB1_GG-: D231.03
D231_MCB1_H+: D231.10
D231_MCB1_H-: D231.09
D231_MCB1_HH+: D231.02
D231_MCB1_HH-: D231.01
D232_MCB1_CT2: D232.17
D232_MCB1_E+: D232.16
D232_MCB1_E-: D232.15
D232_MCB1_EE+: D232.08
D232_MCB1_EE-: D232.07
D232_MCB1_F+: D232.14
D232_MCB1_F-: D232.13
D232_MCB1_FF+: D232.06
D232_MCB1_FF-: D232.05
D232_MCB1_G+: D232.12
D232_MCB1_G-: D232.11
D232_MCB1_GG+: D232.04
D232_MCB1_GG-: D232.03
D232_MCB1_H+: D232.10
D232_MCB1_H-: D232.09
D232_MCB1_HH+: D232.02
D232_MCB1_HH-: D232.01
D431_MCB1_A+: D431.16
D431_MCB1_A-: D431.15
D431_MCB1_AA+: D431.08
D431_MCB1_AA-: D431.07
D431_MCB1_B+: D431.14
D431_MCB1_B-: D431.13
D431_MCB1_BB+: D431.06
D431_MCB1_BB-: D431.05
D431_MCB1_C+: D431.12
D431_MCB1_C-: D431.11
D431_MCB1_CC+: D431.04
D431_MCB1_CC-: D431.03
D431_MCB1_CT1: D431.17
D431_MCB1_D+: D431.10
D431_MCB1_D-: D431.09
D431_MCB1_DD+: D431.02
D431_MCB1_DD-: D431.01
D432_MCB1_A+: D432.16
D432_MCB1_A-: D432.15
D432_MCB1_AA+: D432.08
D432_MCB1_AA-: D432.07
D432_MCB1_B+: D432.14
D432_MCB1_B-: D432.13
D432_MCB1_BB+: D432.06
D432_MCB1_BB-: D432.05
D432_MCB1_C+: D432.12
D432_MCB1_C-: D432.11
D432_MCB1_CC+: D432.04
D432_MCB1_CC-: D432.03
D432_MCB1_CT1: D432.17
D432_MCB1_D+: D432.10
D432_MCB1_D-: D432.09
D432_MCB1_DD+: D432.02
D432_MCB1_DD-: D432.01
D10201: D102.01
D10202: D102.02
D10203: D102.03
D10204: D102.04
D10205: D102.05
D10206: D102.06
D10207: D102.07
D10208: D102.08
D10209: D102.09
D10210: D102.10
D10211: D102.11
D10212: D102.12
D10213: D102.13
D10214: D102.14
D10215: D102.15
D10216: D102.16
D10301: D103.01 SITE1.70(OSD_SPI_SDO)
D10302: D103.02 SITE1.65(LED_SPI_SO_A)
D10303: D103.03 SITE1.66(LED_SPI_SO_B)
D10304: D103.04 RB1.2 UB1.6(SCL)
D10305: D103.05 SITE1.61(LED_SPI_XLAT_B)
D10306: D103.06 RB2.2 UB1.5(SDA)
D10307: D103.07 SITE1.59(LED_SPI_SIN_B)
D10308: D103.08
D10309: D103.09 SITE1.58(LED_SPI_GSCLK_B)
D10310: D103.10
D10311: D103.11 SITE1.55(LED_SPI_SCLK_A)
D10312: D103.12
D10313: D103.13 SITE1.54(LED_SPI_SIN_A)
D10314: D103.14
D10315: D103.15 K13.3 SITE1.67(OSD_SPI_SCK_I2CCLK)
D10316: D103.16
D10401: D104.01 SITE1.56(LED_SPI_XLAT_A)
D10402: D104.02 SITE1.60(LED_SPI_SCLK_B)
D10403: D104.03 SITE1.48(FAIL_FLAG_O)
D10404: D104.04 SITE1.57(LED_SPI_BLANK_B)
D10405: D104.05 SITE1.52(LED_SPI_BLANK_A)
D10406: D104.06 SITE1.53(LED_SPI_GSCLK_A)
D10407: D104.07 SITE1.40(AGEN)
D10408: D104.08 SITE1.49(PWMI)
D10409: D104.09 RP3.2
D10410: D104.10 SITE1.45(STV_IN)
D10411: D104.11 SITE1.69(OSD_SPI_CSN)
D10412: D104.12 SITE1.46(EIO1)
D10413: D104.13 RP9.2
D10414: D104.14 SITE1.47(EIO2)
D10415: D104.15 R118.1 SITE1.148(ISP_LOCK)
D10416: D104.16 K13.6 SITE1.68(OSD_SPI_SDI_I2CDAT)
D10601: D106.01
D10602: D106.02
D10603: D106.03
D10604: D106.04
D10605: D106.05
D10606: D106.06
D10607: D106.07
D10608: D106.08
D10609: D106.09
D10610: D106.10
D10611: D106.11
D10612: D106.12
D10613: D106.13
D10614: D106.14
D10615: D106.15
D10616: D106.16
D10701: D107.01 SITE2.70(OSD_SPI_SDO)
D10702: D107.02 SITE2.65(LED_SPI_SO_A)
D10703: D107.03 SITE2.66(LED_SPI_SO_B)
D10704: D107.04
D10705: D107.05 SITE2.61(LED_SPI_XLAT_B)
D10706: D107.06
D10707: D107.07 SITE2.59(LED_SPI_SIN_B)
D10708: D107.08
D10709: D107.09 SITE2.58(LED_SPI_GSCLK_B)
D10710: D107.10
D10711: D107.11 SITE2.55(LED_SPI_SCLK_A)
D10712: D107.12
D10713: D107.13 SITE2.54(LED_SPI_SIN_A)
D10714: D107.14
D10715: D107.15 SITE2.67(OSD_SPI_SCK_I2CCLK) UNK2K13.3
D10716: D107.16
D10801: D108.01 SITE2.56(LED_SPI_XLAT_A)
D10802: D108.02 SITE2.60(LED_SPI_SCLK_B)
D10803: D108.03 SITE2.48(FAIL_FLAG_O)
D10804: D108.04 SITE2.57(LED_SPI_BLANK_B)
D10805: D108.05 SITE2.52(LED_SPI_BLANK_A)
D10806: D108.06 SITE2.53(LED_SPI_GSCLK_A)
D10807: D108.07 SITE2.40(AGEN)
D10808: D108.08 SITE2.49(PWMI)
D10809: D108.09 UNK2RP3.2
D10810: D108.10 SITE2.45(STV_IN)
D10811: D108.11 SITE2.69(OSD_SPI_CSN)
D10812: D108.12 SITE2.46(EIO1)
D10813: D108.13 UNK2RP9.2
D10814: D108.14 SITE2.47(EIO2)
D10815: D108.15 SITE2.148(ISP_LOCK) UNK2R118.1
D10816: D108.16 SITE2.68(OSD_SPI_SDI_I2CDAT) UNK2K13.6
D10901: D109.01 SITE2.91(BML1P) UNK2R23.1
D10902: D109.02 SITE2.87(AML5P) UNK2R19.1
D10903: D109.03 SITE2.92(BML1N) UNK2R24.2
D10904: D109.04 SITE2.88(AML5N) UNK2R20.2
D10905: D109.05 SITE2.75(AML1P) UNK2R9.1
D10906: D109.06 SITE2.98(BML3P) UNK2R29.1
D10907: D109.07 SITE2.76(AML1N) UNK2R10.2
D10908: D109.08 SITE2.99(BML3N) UNK2R30.2
D10909: D109.09 SITE2.93(BML2P) UNK2R25.1
D10910: D109.10 SITE2.122(CML3P) UNK2R67.1
D10911: D109.11 SITE2.94(BML2N) UNK2R26.2
D10912: D109.12 SITE2.123(CML3N) UNK2R68.2
D10913: D109.13 SITE2.95(BMLCKP) UNK2R27.1
D10914: D109.14 SITE2.124(CML4P) UNK2R69.1
D10915: D109.15 SITE2.96(BMLCKN) UNK2R28.2
D10916: D109.16 SITE2.125(CML4N) UNK2R70.2
D11001: D110.01 SITE2.79(AML2P) UNK2R11.1
D11002: D110.02 SITE2.116(CML2P) UNK2R39.1
D11003: D110.03 SITE2.80(AML2N) UNK2R12.2
D11004: D110.04 SITE2.117(CML2N) UNK2R40.2
D11005: D110.05 SITE2.73(AML0P) UNK2R7.1
D11006: D110.06 SITE2.120(CMLCKP) UNK2R41.1
D11007: D110.07 SITE2.74(AML0N) UNK2R8.2
D11008: D110.08 SITE2.121(CMLCKN) UNK2R42.2
D11009: D110.09 SITE2.100(BML4P) UNK2R31.1
D11010: D110.10 SITE2.135(DMLCKP) UNK2R79.1
D11011: D110.11 SITE2.101(BML4N) UNK2R32.2
D11012: D110.12 SITE2.136(DMLCKN) UNK2R80.2
D11013: D110.13 SITE2.102(BML5P) UNK2R33.1
D11014: D110.14 SITE2.137(DML3P) UNK2R43.1
D11015: D110.15 SITE2.103(BML5N) UNK2R34.2
D11016: D110.16 SITE2.138(DML3N) UNK2R44.2
D11101: D111.01 SITE2.129(DML0P) UNK2R73.1
D11102: D111.02 SITE2.81(AMLCKP) UNK2R13.1
D11103: D111.03 SITE2.130(DML0N) UNK2R74.2
D11104: D111.04 SITE2.82(AMLCKN) UNK2R14.2
D11105: D111.05 SITE2.126(CML5P) UNK2R71.1
D11106: D111.06 SITE2.83(AML3P) UNK2R15.1
D11107: D111.07 SITE2.127(CML5N) UNK2R72.2
D11108: D111.08 SITE2.84(AML3N) UNK2R16.2
D11109: D111.09 SITE2.112(CML0P) UNK2R35.1
D11110: D111.10 SITE2.85(AML4P) UNK2R17.1
D11111: D111.11 SITE2.113(CML0N) UNK2R36.2
D11112: D111.12 SITE2.86(AML4N) UNK2R18.2
D11113: D111.13 SITE2.114(CML1P) UNK2R37.1
D11114: D111.14 SITE2.89(BML0P) UNK2R21.1
D11115: D111.15 SITE2.115(CML1N) UNK2R38.2
D11116: D111.16 SITE2.90(BML0N) UNK2R22.2
D11201: D112.01 UNK2K18.7
D11202: D112.02 UNK2RT1.2 UNK2UT1.2
D11203: D112.03 UNK2K18.2
D11204: D112.04 UNK2RT2.2 UNK2UT1.1
D11205: D112.05 UNK2RP7.2
D11206: D112.06 SITE2.77(NC_VDDTX_11_B)
D11207: D112.07 UNK2RP10.2
D11208: D112.08 UNK2RP6.2
D11209: D112.09 SITE2.142(DML5P) UNK2R100.1
D11210: D112.10 SITE2.131(DML1P) UNK2R75.1
D11211: D112.11 SITE2.143(DML5N) UNK2R101.2
D11212: D112.12 SITE2.132(DML1N) UNK2R76.2
D11213: D112.13 SITE2.140(DML4P) UNK2R63.1
D11214: D112.14 SITE2.133(DML2P) UNK2R77.1
D11215: D112.15 SITE2.141(DML4N) UNK2R64.2
D11216: D112.16 SITE2.134(DML2N) UNK2R78.2
D11301: D113.01 R13.1 SITE1.81(AMLCKP)
D11302: D113.02 R21.1 SITE1.89(BML0P)
D11303: D113.03 R14.2 SITE1.82(AMLCKN)
D11304: D113.04 R22.2 SITE1.90(BML0N)
D11305: D113.05 R11.1 SITE1.79(AML2P)
D11306: D113.06 R19.1 SITE1.87(AML5P)
D11307: D113.07 R12.2 SITE1.80(AML2N)
D11308: D113.08 R20.2 SITE1.88(AML5N)
D11309: D113.09 R23.1 SITE1.91(BML1P)
D11310: D113.10 R29.1 SITE1.98(BML3P)
D11311: D113.11 R24.2 SITE1.92(BML1N)
D11312: D113.12 R30.2 SITE1.99(BML3N)
D11313: D113.13 R7.1 SITE1.73(AML0P)
D11314: D113.14 R41.1 SITE1.120(CMLCKP)
D11315: D113.15 R8.2 SITE1.74(AML0N)
D11316: D113.16 R42.2 SITE1.121(CMLCKN)
D11401: D114.01 R39.1 SITE1.116(CML2P)
D11402: D114.02 R33.1 SITE1.102(BML5P)
D11403: D114.03 R40.2 SITE1.117(CML2N)
D11404: D114.04 R34.2 SITE1.103(BML5N)
D11405: D114.05 R35.1 SITE1.112(CML0P)
D11406: D114.06 R31.1 SITE1.100(BML4P)
D11407: D114.07 R36.2 SITE1.113(CML0N)
D11408: D114.08 R32.2 SITE1.101(BML4N)
D11409: D114.09 R25.1 SITE1.93(BML2P)
D11410: D114.10 R77.1 SITE1.133(DML2P)
D11411: D114.11 R26.2 SITE1.94(BML2N)
D11412: D114.12 R78.2 SITE1.134(DML2N)
D11413: D114.13 R27.1 SITE1.95(BMLCKP)
D11414: D114.14 R75.1 SITE1.131(DML1P)
D11415: D114.15 R28.2 SITE1.96(BMLCKN)
D11416: D114.16 R76.2 SITE1.132(DML1N)
D11501: D115.01 R69.1 SITE1.124(CML4P)
D11502: D115.02 R9.1 SITE1.75(AML1P)
D11503: D115.03 R70.2 SITE1.125(CML4N)
D11504: D115.04 R10.2 SITE1.76(AML1N)
D11505: D115.05 R71.1 SITE1.126(CML5P)
D11506: D115.06 R15.1 SITE1.83(AML3P)
D11507: D115.07 R72.2 SITE1.127(CML5N)
D11508: D115.08 R16.2 SITE1.84(AML3N)
D11509: D115.09 R67.1 SITE1.122(CML3P)
D11510: D115.10 R17.1 SITE1.85(AML4P)
D11511: D115.11 R68.2 SITE1.123(CML3N)
D11512: D115.12 R18.2 SITE1.86(AML4N)
D11513: D115.13 R37.1 SITE1.114(CML1P)
D11514: D115.14 R73.1 SITE1.129(DML0P)
D11515: D115.15 R38.2 SITE1.115(CML1N)
D11516: D115.16 R74.2 SITE1.130(DML0N)
D11601: D116.01 K18.7
D11602: D116.02 RT1.2 UT1.2(SDA)
D11603: D116.03 K18.2
D11604: D116.04 RT2.2 UT1.1(SCL)
D11605: D116.05 RP7.2
D11606: D116.06 SITE1.77(NC_VDDTX_11_B)
D11607: D116.07 RP10.2
D11608: D116.08 RP6.2
D11609: D116.09 R43.1 SITE1.137(DML3P)
D11610: D116.10 R63.1 SITE1.140(DML4P)
D11611: D116.11 R44.2 SITE1.138(DML3N)
D11612: D116.12 R64.2 SITE1.141(DML4N)
D11613: D116.13 R79.1 SITE1.135(DMLCKP)
D11614: D116.14 R100.1 SITE1.142(DML5P)
D11615: D116.15 R80.2 SITE1.136(DMLCKN)
D11616: D116.16 R101.2 SITE1.143(DML5N)
D11701: D117.01 K10.3 S1_RST_N.1 SITE1.19(RESET_N)
D11702: D117.02 R58.2 SITE1.170(OLV1P)
D11703: D117.03 RT10.1
D11704: D117.04 R57.1 SITE1.169(OLV1N)
D11705: D117.05 J5.2 K28.6 S1_I2C.2 SITE1.51(I2C_SDA)
D11706: D117.06 R56.2 SITE1.168(OLV0P)
D11707: D117.07 RT9.1 RT10.2
D11708: D117.08 R55.1 SITE1.167(OLV0N)
D11709: D117.09 J4.2 K28.3 S1_I2C.1 SITE1.50(I2C_SCL)
D11710: D117.10 R66.2 SITE1.176(OLV3P)
D11711: D117.11 RP12.2
D11712: D117.12 R65.1 SITE1.175(OLV3N)
D11713: D117.13 R62.2 SITE1.174(OLVCKP)
D11714: D117.14 R105.2 SITE1.172(OLV2P)
D11715: D117.15 R61.1 SITE1.173(OLVCKN)
D11716: D117.16 R104.1 SITE1.171(OLV2N)
D11801: C3.2 D118.01
D11802: D118.02 R60.2 SITE1.2(OLV4P)
D11803: C4.2 D118.03
D11804: D118.04 R59.1 SITE1.1(OLV4N)
D11805: D118.05 R50.2 SITE1.16(ELV4P)
D11806: D118.06 R103.2 SITE1.6(ELV0P)
D11807: D118.07 R49.1 SITE1.15(ELV4N)
D11808: D118.08 R102.1 SITE1.5(ELV0N)
D11809: D118.09 R48.2 SITE1.14(ELV3P)
D11810: D118.10 R46.2 SITE1.8(ELV1P)
D11811: D118.11 R47.1 SITE1.13(ELV3N)
D11812: D118.12 R45.1 SITE1.7(ELV1N)
D11813: D118.13 R54.2 SITE1.12(ELVCKP)
D11814: D118.14 R52.2 SITE1.10(ELV2P)
D11815: D118.15 R53.1 SITE1.11(ELVCKN)
D11816: D118.16 R51.1 SITE1.9(ELV2N)
D11901: D119.01 SITE1.165(H2POL)
D11902: D119.02 SITE1.149(OE2)
D11903: D119.03 SITE1.166(SQINV)
D11904: D119.04 SITE1.153(CLK6)
D11905: D119.05 RP2.2
D11906: D119.06 SITE1.152(CLK7)
D11907: D119.07 SITE1.158(CLK1)
D11908: D119.08 SITE1.157(CLK2)
D11909: D119.09 SITE1.154(CLK5)
D11910: D119.10 SITE1.156(CLK3)
D11911: D119.11 SITE1.151(CLK8)
D11912: D119.12 SITE1.161(POL)
D11913: D119.13 SITE1.155(CLK4)
D11914: D119.14 SITE1.160(STV1)
D11915: D119.15 SITE1.163(TP1)
D11916: D119.16 SITE1.159(STV2)
D12001: D120.01 RP5.2
D12002: D120.02 RP1.2
D12003: D120.03 RP4.2
D12004: D120.04 SITE1.164(DC_EN)
D12005: D120.05 K14.2
D12006: D120.06 SITE1.150(OE1)
D12007: D120.07 K14.7
D12008: D120.08 RP11.2
D12009: D120.09 K15.2
D12010: D120.10 SITE1.118(NC_VDDTX_11_T)
D12011: D120.11 K15.7
D12012: D120.12 RP8.2
D12013: D120.13 K9.2
D12014: D120.14 SITE1.18(TEST)
D12015: D120.15 K9.7
D12016: D120.16 SITE1.24(HPD)
D12101: D121.01 SITE2.156(CLK3)
D12102: D121.02 SITE2.176(OLV3P) UNK2R66.2
D12103: D121.03 SITE2.157(CLK2)
D12104: D121.04 SITE2.175(OLV3N) UNK2R65.1
D12105: D121.05 SITE2.152(CLK7)
D12106: D121.06 SITE2.170(OLV1P) UNK2R58.2
D12107: D121.07 SITE2.153(CLK6)
D12108: D121.08 SITE2.169(OLV1N) UNK2R57.1
D12109: D121.09 SITE2.149(OE2)
D12110: D121.10 SITE2.168(OLV0P) UNK2R56.2
D12111: D121.11 UNK2RP12.2
D12112: D121.12 SITE2.167(OLV0N) UNK2R55.1
D12113: D121.13 SITE2.174(OLVCKP) UNK2R62.2
D12114: D121.14 SITE2.172(OLV2P) UNK2R105.2
D12115: D121.15 SITE2.173(OLVCKN) UNK2R61.1
D12116: D121.16 SITE2.171(OLV2N) UNK2R104.1
D12201: D122.01 UNK2C3.2
D12202: D122.02 SITE2.2(OLV4P) UNK2R60.2
D12203: D122.03 UNK2C4.2
D12204: D122.04 SITE2.1(OLV4N) UNK2R59.1
D12205: D122.05 SITE2.16(ELV4P) UNK2R50.2
D12206: D122.06 SITE2.6(ELV0P) UNK2R103.2
D12207: D122.07 SITE2.15(ELV4N) UNK2R49.1
D12208: D122.08 SITE2.5(ELV0N) UNK2R102.1
D12209: D122.09 SITE2.14(ELV3P) UNK2R48.2
D12210: D122.10 SITE2.8(ELV1P) UNK2R46.2
D12211: D122.11 SITE2.13(ELV3N) UNK2R47.1
D12212: D122.12 SITE2.7(ELV1N) UNK2R45.1
D12213: D122.13 SITE2.10(ELV2P) UNK2R52.2
D12214: D122.14 SITE2.12(ELVCKP) UNK2R54.2
D12215: D122.15 SITE2.9(ELV2N) UNK2R51.1
D12216: D122.16 SITE2.11(ELVCKN) UNK2R53.1
D12301: D123.01 SITE2.118(NC_VDDTX_11_T)
D12302: D123.02 SITE2.161(POL)
D12303: D123.03 UNK2RP11.2
D12304: D123.04 SITE2.160(STV1)
D12305: D123.05 SITE2.150(OE1)
D12306: D123.06 SITE2.159(STV2)
D12307: D123.07 SITE2.164(DC_EN)
D12308: D123.08 SITE2.163(TP1)
D12309: D123.09 UNK2RP1.2
D12310: D123.10 SITE2.155(CLK4)
D12311: D123.11 SITE2.165(H2POL)
D12312: D123.12 SITE2.151(CLK8)
D12313: D123.13 SITE2.166(SQINV)
D12314: D123.14 SITE2.154(CLK5)
D12315: D123.15 UNK2RP2.2
D12316: D123.16 SITE2.158(CLK1)
D12401: D124.01 UNK2RT10.1
D12402: D124.02 UNK2RP8.2
D12403: D124.03 UNK2RT9.1 UNK2RT10.2
D12404: D124.04 SITE2.18(TEST)
D12405: D124.05 SITE2.50(I2C_SCL) UNK2J4.2 UNK2K28.3 UNK2S1_I2C.1
D12406: D124.06 UNK2K9.2
D12407: D124.07 SITE2.51(I2C_SDA) UNK2J5.2 UNK2K28.6 UNK2S1_I2C.2
D12408: D124.08 UNK2K9.7
D12409: D124.09 SITE2.19(RESET_N) UNK2K10.3 UNK2S1_RST_N.1
D12410: D124.10 SITE2.24(HPD)
D12411: D124.11 UNK2K14.2
D12412: D124.12 UNK2RP4.2
D12413: D124.13 UNK2K14.7
D12414: D124.14 UNK2RP5.2
D12415: D124.15 UNK2K15.2
D12416: D124.16 UNK2K15.7
D23004: D230.04
D30101: D301.01
D30102: D301.02 SITE1.26(RXD0P)
D30103: D301.03
D30104: D301.04 SITE1.27(RXD0N)
